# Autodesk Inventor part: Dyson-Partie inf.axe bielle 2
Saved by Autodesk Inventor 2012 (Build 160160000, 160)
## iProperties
Created: 2012-11
Part Number: Dyson-Partie inf.axe bielle 2
Material: Default
Document SubType Name: Modeling
Designer: Administrateur
Density: 1 g/cm^3
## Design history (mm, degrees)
node "Dyson-Partie inf.axe bielle 21"
node "Dyson-Partie inf.axe bielle 2"
node "Base1"
